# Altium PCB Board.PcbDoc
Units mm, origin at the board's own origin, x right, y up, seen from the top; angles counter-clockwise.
Board outline 30 x 20 mm, 2 copper layers (Top, Bottom), stack 0 mm thick; 3 components, 3 nets, 12 pads, 0 vias.
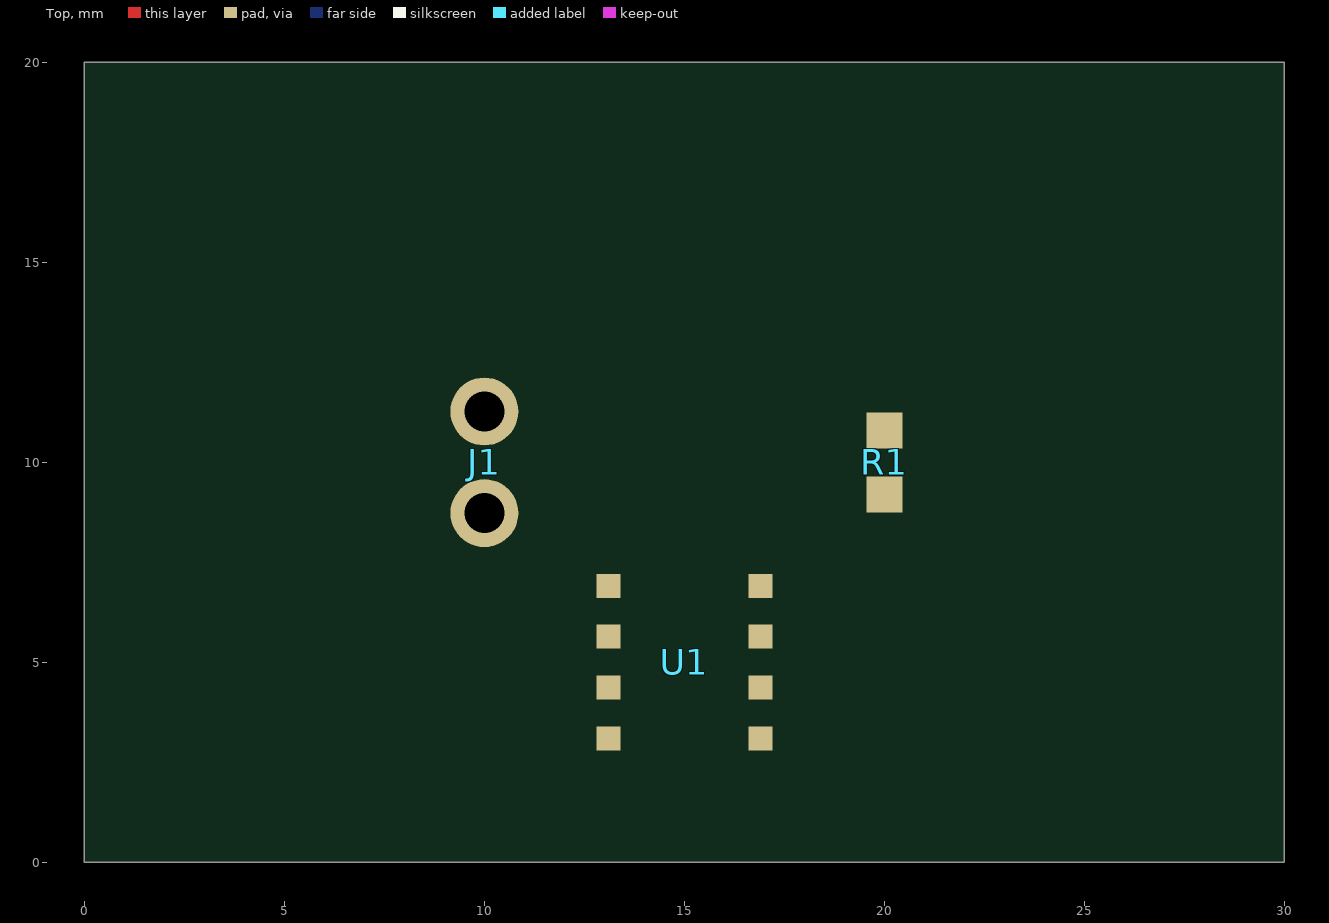
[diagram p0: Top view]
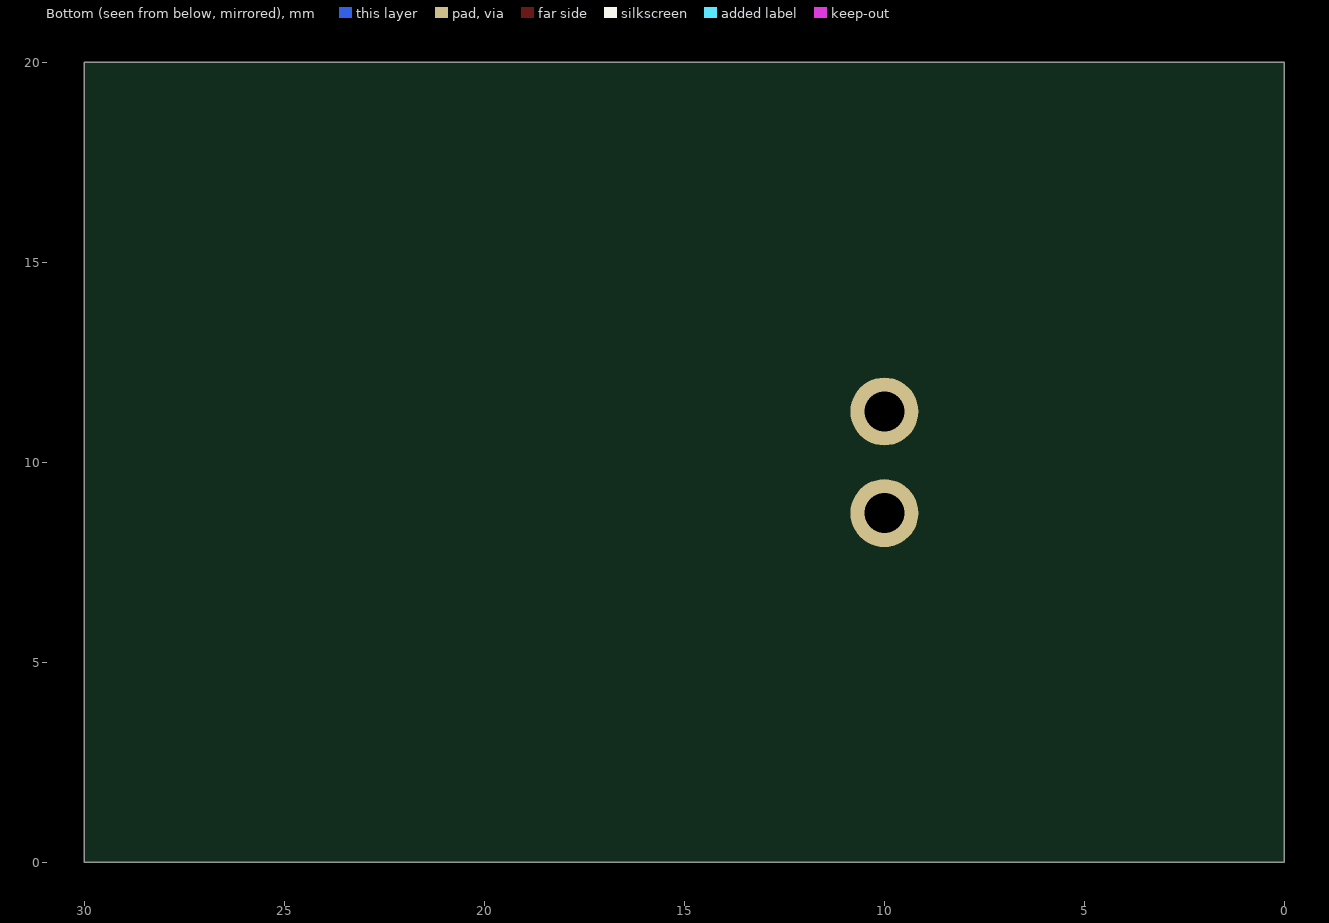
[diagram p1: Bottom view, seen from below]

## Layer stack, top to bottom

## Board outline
0,0 30,0 30,20 0,20

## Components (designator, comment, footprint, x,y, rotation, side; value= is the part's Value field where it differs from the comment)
J1 "" HDR1X2 10,10 r0 top
R1 "" R0603 20,10 r90 top
U1 "" SOIC8 15,5 r0 top

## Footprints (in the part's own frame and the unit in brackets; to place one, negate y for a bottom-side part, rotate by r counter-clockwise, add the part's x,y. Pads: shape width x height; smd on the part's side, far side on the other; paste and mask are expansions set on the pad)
HDR1X2 [mm]
  round 1.7 hole 1: 1(0,-1.27) 2(0,1.27)
  body extent -1.27,-2.54 1.27,2.54, height 8.5
R0603 [mm]
  rect 0.9x0.9 smd: 1(-0.8,0) 2(0.8,0)
  body extent -0.4,-0.8 0.4,0.8, height 0.45
SOIC8 [mm]
  rect 0.6x0.6 smd: 1(-1.9,-1.9) 2(-1.9,-0.63) 3(-1.9,0.64) 4(-1.9,1.91) 5(1.9,1.91) 6(1.9,0.64) 7(1.9,-0.63) 8(1.9,-1.9)

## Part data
J1: library part "Header 2"
R1: library part Res
U1: library part OPA2333

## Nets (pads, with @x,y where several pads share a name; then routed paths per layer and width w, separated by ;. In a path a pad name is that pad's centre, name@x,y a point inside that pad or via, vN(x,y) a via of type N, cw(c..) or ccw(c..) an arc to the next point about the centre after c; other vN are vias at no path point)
FB: R1.1 U1.5 U1.6 U1.7 U1.8
GND: J1.2 R1.2 U1.1 U1.2 U1.3 U1.4
V3V3: J1.1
